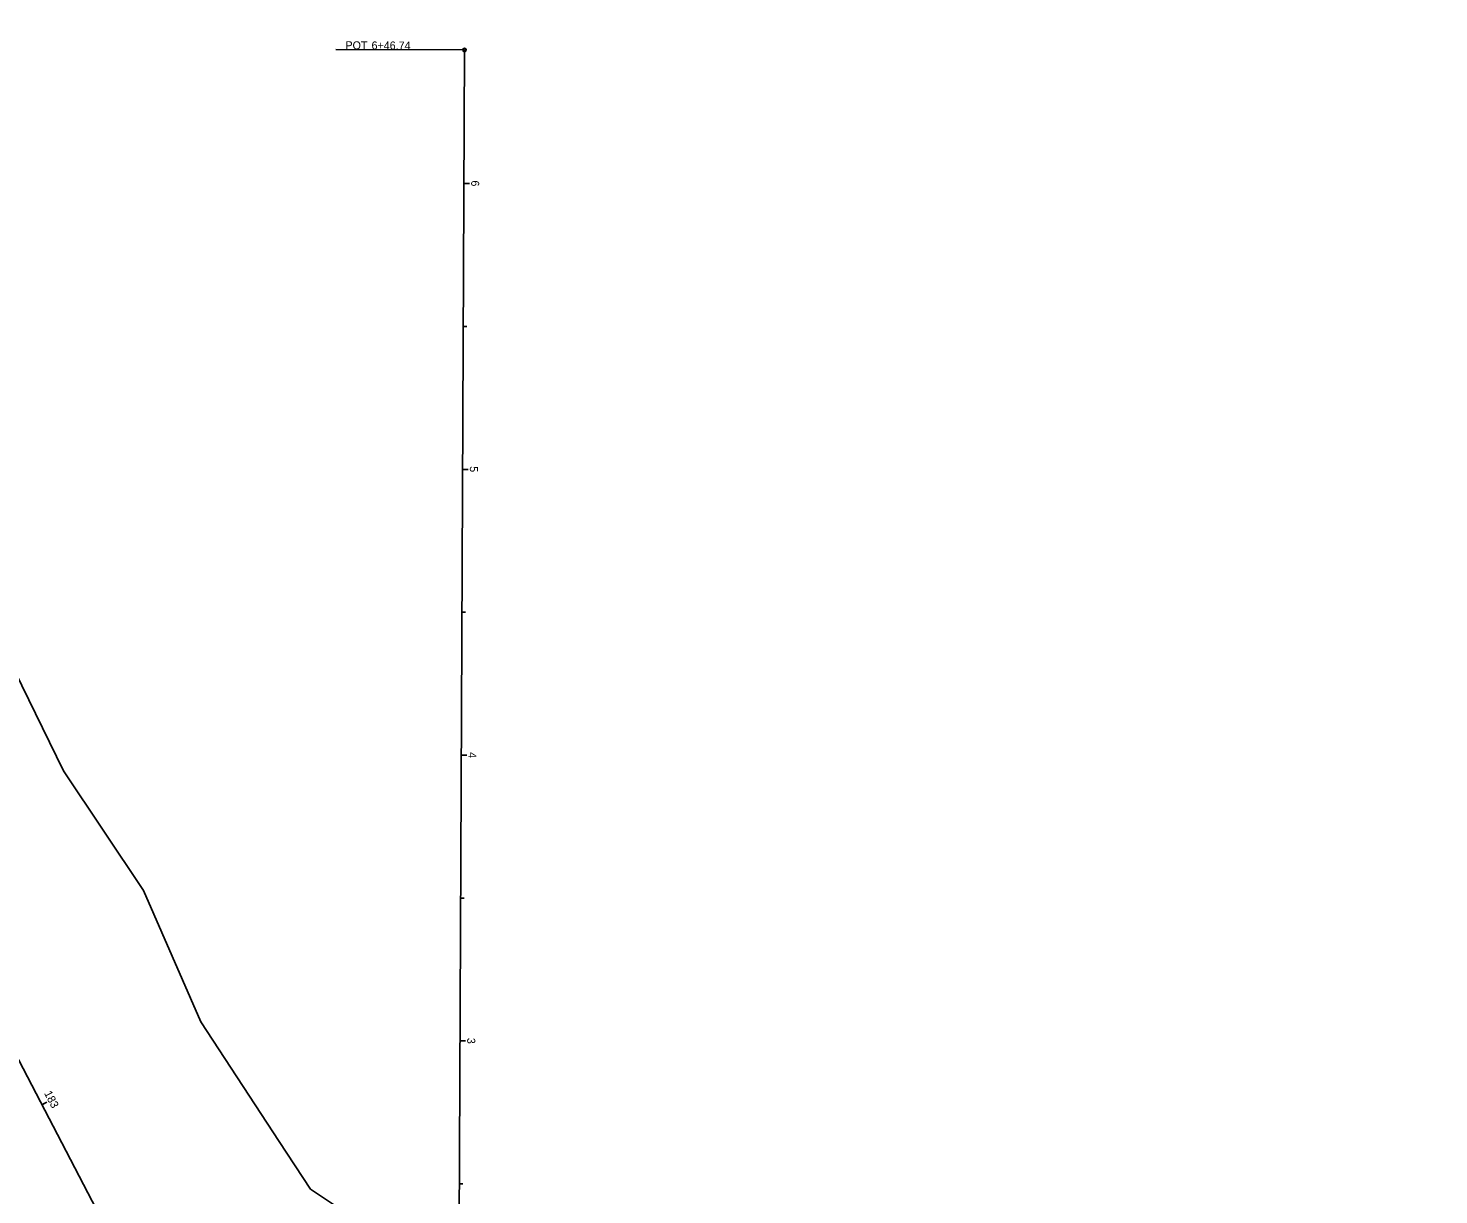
# Model space of a CAD drawing. Extents: x 2297881 to 2300632, y 559916 to 564460.
# Drawn here: x 2298903.2 to 2299396.6, y 562752.3 to 563160.5 of the extents above; entities that cross this region are included whole.
import ezdxf

# ---------------------------------------------------------------- set-up
doc = ezdxf.new("R2010")
doc.units = 0
for name, color, linetype in [('DT_P_Tie', 7, 'Continuous'), ('GE_X_Alignment', 7, 'Continuous'), ('GE_X_Alignment_1000_Cardinal_Points', 7, 'Continuous'), ('GE_X_Alignment_1000_Stations', 7, 'Continuous'), ('GE_X_Alignment_100_Cardinal_Points', 7, 'Continuous'), ('GE_X_Alignment_100_Stations', 7, 'Continuous'), ('GE_X_Alignment_500_Cardinal_Points', 7, 'Continuous'), ('GE_X_Alignment_500_Stations', 7, 'Continuous')]:
    doc.layers.add(name, color=color, linetype=linetype)

msp = doc.modelspace()

# ---------------------------------------------------------------- linework, layer by layer
at = {"layer": 'DT_P_Tie'}
for points in [[(2298519.78, 563607.1), (2298532.66, 563592.38), (2298536.2, 563588.33), (2298552.62, 563557.18), (2298576.68, 563513.38), (2298601.74, 563470.09), (2298627.12, 563426.87), (2298649.29, 563382.07), (2298675.9, 563339.67), (2298702.63, 563297.13), (2298725.66, 563252.62), (2298747.5, 563207.67), (2298772.38, 563164.38), (2298799.21, 563121.95), (2298822.79, 563077.77), (2298846.25, 563033.48), (2298864.47, 562986.74), (2298893.61, 562945.63), (2298915.5, 562900.63), (2298943.54, 562858.82), (2298963.55, 562812.85), (2298990.94, 562770.94), (2299002, 562754.27)], [(2299002, 562754.27), (2299033.84, 562733.04), (2299055.45, 562691.62)]]:
    msp.add_lwpolyline(points, dxfattribs=at)
at = {"layer": 'GE_X_Alignment'}
for p, q in [((2298386.28, 563783.36), (2299396.64, 561847.4)), ((2299052.83, 562506.17), (2299055.84, 563152.91)), ((2299052.83, 562506.17), (2299055.84, 563152.91))]:
    msp.add_line(p, q, dxfattribs=at)
at = {"layer": 'GE_X_Alignment_1000_Cardinal_Points'}
msp.add_line((2299055.84, 563152.91), (2299010.84, 563153.11), dxfattribs=at)
msp.add_circle((2299055.84, 563152.91), 0.6, dxfattribs=at)
at = {"layer": 'GE_X_Alignment_1000_Stations'}
msp.add_line((2299055.16, 563006.16), (2299056.36, 563006.16), dxfattribs=at)
at = {"layer": 'GE_X_Alignment_100_Cardinal_Points'}
msp.add_line((2299055.84, 563152.91), (2299010.84, 563153.11), dxfattribs=at)
msp.add_circle((2299055.84, 563152.91), 0.6, dxfattribs=at)
at = {"layer": 'GE_X_Alignment_100_Stations'}
for p, q in [((2299055.62, 563106.16), (2299057.62, 563106.15)), ((2299055.39, 563056.16), (2299056.59, 563056.16)), ((2299055.16, 563006.16), (2299057.16, 563006.15)), ((2299054.92, 562956.16), (2299056.12, 562956.16)), ((2299054.69, 562906.17), (2299056.69, 562906.16)), ((2299054.46, 562856.17), (2299055.66, 562856.16)), ((2299054.23, 562806.17), (2299056.23, 562806.16)), ((2298907.94, 562783.79), (2298909.72, 562784.72)), ((2299053.99, 562756.17), (2299055.19, 562756.16))]:
    msp.add_line(p, q, dxfattribs=at)
at = {"layer": 'GE_X_Alignment_500_Cardinal_Points'}
msp.add_line((2299055.84, 563152.91), (2299010.84, 563153.11), dxfattribs=at)
msp.add_circle((2299055.84, 563152.91), 0.6, dxfattribs=at)
at = {"layer": 'GE_X_Alignment_500_Stations'}
for p, q in [((2299055.62, 563106.16), (2299056.82, 563106.16)), ((2299055.16, 563006.16), (2299057.16, 563006.15)), ((2299054.69, 562906.17), (2299055.89, 562906.16)), ((2299054.23, 562806.17), (2299055.43, 562806.16)), ((2298907.94, 562783.79), (2298909.01, 562784.35))]:
    msp.add_line(p, q, dxfattribs=at)

# ---------------------------------------------------------------- texts
at = {"layer": 'GE_X_Alignment_1000_Cardinal_Points'}
for s, p in [('POT', (2299014.17, 563153.15)), ('6+46.74', (2299023.3, 563153.1))]:
    msp.add_text(s, height=2.8, rotation=359.7339, dxfattribs=at).set_placement(p)
at = {"layer": 'GE_X_Alignment_100_Cardinal_Points'}
for s, p in [('POT', (2299014.17, 563153.15)), ('6+46.74', (2299023.3, 563153.1))]:
    msp.add_text(s, height=2.8, rotation=359.7339, dxfattribs=at).set_placement(p)
at = {"layer": 'GE_X_Alignment_100_Stations'}
for s, rotation, p in [('6', 269.7339, (2299058.17, 563107.26)), ('5', 269.7339, (2299057.71, 563007.27)), ('4', 269.7339, (2299057.2, 562907.22)), ('3', 269.7339, (2299056.78, 562807.24)), ('183', 297.5598, (2298908.69, 562787.87))]:
    msp.add_text(s, height=2.8, rotation=rotation, dxfattribs=at).set_placement(p)
at = {"layer": 'GE_X_Alignment_500_Cardinal_Points'}
for s, p in [('POT', (2299014.17, 563153.15)), ('6+46.74', (2299023.3, 563153.1))]:
    msp.add_text(s, height=2.8, rotation=359.7339, dxfattribs=at).set_placement(p)
at = {"layer": 'GE_X_Alignment_500_Stations'}
msp.add_text('5', height=2.8, rotation=269.7339, dxfattribs=at).set_placement((2299057.71, 563007.27))

doc.saveas('drawing.dxf')
